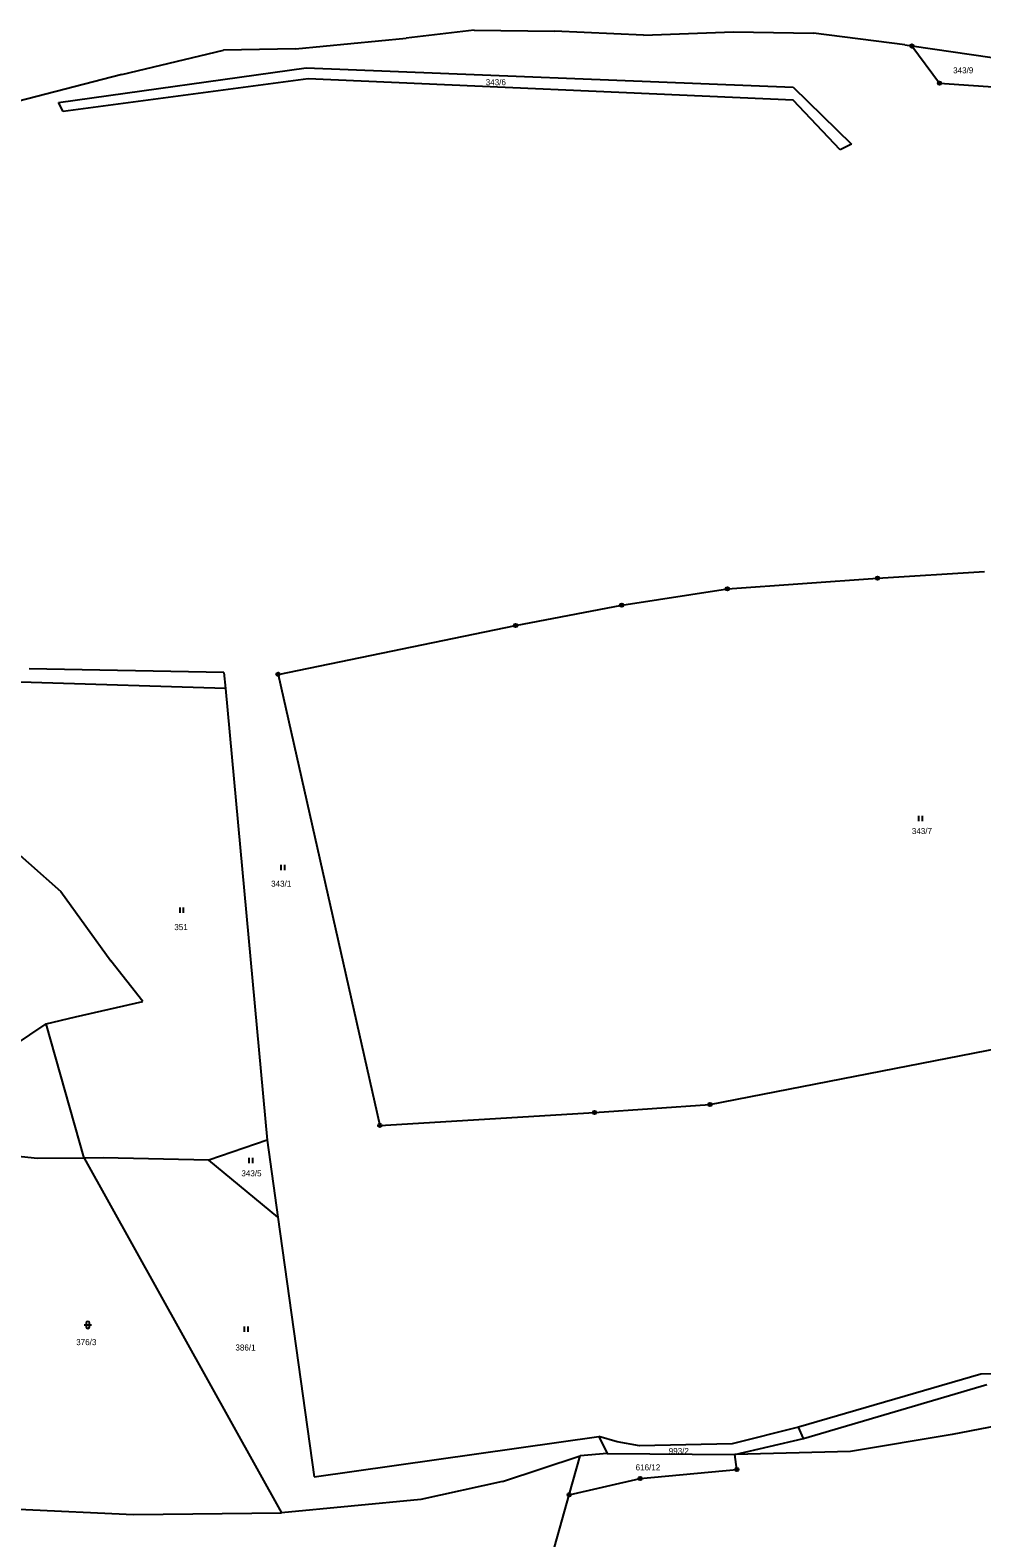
# Model space of a CAD drawing. Extents: x -754970 to -752637, y -970569 to -968179.
# Drawn here: x -754459.1 to -754191, y -968939.8 to -968515.2 of the extents above; entities that cross this region are included whole.
import ezdxf
from ezdxf.enums import TextEntityAlignment as Align

# ---------------------------------------------------------------- set-up
doc = ezdxf.new("R2010")
doc.units = 0
doc.header["$LTSCALE"] = 0.68
for name, color, linetype, lineweight in [('1', 7, 'Continuous', 25), ('3', 7, 'Continuous', 25), ('8', 7, 'Continuous', 25)]:
    doc.layers.add(name, color=color, linetype=linetype, lineweight=lineweight)
doc.layers.add('2', color=7, linetype='Continuous')

msp = doc.modelspace()

# ---------------------------------------------------------------- linework, layer by layer
at = {"layer": '1'}
for p, q in [((-754334.06, -968515.2), (-754353.18, -968517.43)), ((-754334.06, -968515.2), (-754311.42, -968515.52)), ((-754286.27, -968516.63), (-754311.42, -968515.52)), ((-754286.27, -968516.63), (-754260.98, -968515.67)), ((-754260.98, -968515.67), (-754238.42, -968516.06)), ((-754212.69, -968519.37), (-754238.42, -968516.06)), ((-754384.36, -968520.42), (-754353.18, -968517.43)), ((-754212.69, -968519.37), (-754210.71, -968519.66)), ((-754210.71, -968519.66), (-754188.09, -968522.93)), ((-754210.71, -968519.66), (-754202.9, -968530.13)), ((-754433.35, -968527.73), (-754404.65, -968520.82)), ((-754384.36, -968520.42), (-754404.65, -968520.82)), ((-754433.35, -968527.73), (-754462.74, -968535.32)), ((-754451.15, -968535.59), (-754381.35, -968525.78)), ((-754381.35, -968525.78), (-754244.11, -968531.24)), ((-754380.77, -968528.88), (-754449.8, -968538.11)), ((-754244.18, -968534.92), (-754380.77, -968528.88)), ((-754244.11, -968531.24), (-754227.7, -968547.33)), ((-754202.9, -968530.13), (-754183.76, -968531.43)), ((-754449.8, -968538.11), (-754451.15, -968535.59)), ((-754230.91, -968548.91), (-754244.18, -968534.92)), ((-754227.7, -968547.33), (-754230.91, -968548.91)), ((-754220.37, -968669.52), (-754190.19, -968667.68)), ((-754292.45, -968677.13), (-754262.67, -968672.55)), ((-754262.67, -968672.55), (-754220.37, -968669.52)), ((-754322.36, -968682.86), (-754292.45, -968677.13)), ((-754389.3, -968696.62), (-754322.36, -968682.86)), ((-754458.84, -968698.91), (-754526.43, -968697.59)), ((-754404.56, -968696.08), (-754459.46, -968695.1)), ((-754404.56, -968696.08), (-754404.12, -968700.59)), ((-754389.3, -968696.62), (-754360.62, -968823.65)), ((-754404.12, -968700.59), (-754458.84, -968698.91)), ((-754404.12, -968700.59), (-754392.37, -968827.82)), ((-754499.27, -968714.58), (-754450.52, -968757.76)), ((-754450.52, -968757.76), (-754436.37, -968777.32)), ((-754427.43, -968788.74), (-754436.37, -968777.32)), ((-754446.37, -968793.08), (-754427.43, -968788.74)), ((-754470.43, -968805.64), (-754454.59, -968795.02)), ((-754454.59, -968795.02), (-754446.37, -968793.08)), ((-754443.88, -968832.87), (-754454.59, -968795.02)), ((-754267.58, -968817.77), (-754185.68, -968801.8)), ((-754360.62, -968823.65), (-754300.13, -968820)), ((-754300.13, -968820), (-754267.58, -968817.77)), ((-754457.06, -968832.97), (-754499.36, -968828.55)), ((-754392.37, -968827.82), (-754408.84, -968833.4)), ((-754392.37, -968827.82), (-754389.33, -968849.47)), ((-754443.88, -968832.87), (-754457.06, -968832.97)), ((-754438.57, -968832.78), (-754443.88, -968832.87)), ((-754443.88, -968832.87), (-754388.34, -968932.75)), ((-754408.84, -968833.4), (-754438.57, -968832.78)), ((-754389.33, -968849.47), (-754408.84, -968833.4)), ((-754389.33, -968849.47), (-754379.07, -968922.66)), ((-754191.24, -968893.69), (-754242.67, -968908.61)), ((-754136.79, -968893.18), (-754191.24, -968893.69)), ((-754241.27, -968911.79), (-754189.58, -968896.62)), ((-754150.53, -968901.2), (-754199.37, -968910.74)), ((-754242.67, -968908.61), (-754261.37, -968913.34)), ((-754241.27, -968911.79), (-754242.67, -968908.61)), ((-754199.37, -968910.74), (-754227.98, -968915.46)), ((-754379.07, -968922.66), (-754298.86, -968911.22)), ((-754298.86, -968911.22), (-754296.56, -968916.06)), ((-754293.73, -968912.8), (-754298.86, -968911.22)), ((-754287.44, -968913.88), (-754293.73, -968912.8)), ((-754261.37, -968913.34), (-754287.44, -968913.88)), ((-754260.6, -968916.29), (-754241.27, -968911.79)), ((-754326.03, -968923.97), (-754304.17, -968916.69)), ((-754307.25, -968927.67), (-754304.17, -968916.69)), ((-754296.56, -968916.06), (-754304.17, -968916.69)), ((-754296.56, -968916.06), (-754260.6, -968916.29)), ((-754227.98, -968915.46), (-754260.6, -968916.29)), ((-754260.01, -968920.54), (-754260.6, -968916.29)), ((-754307.25, -968927.67), (-754287.26, -968923.08)), ((-754287.26, -968923.08), (-754260.01, -968920.54)), ((-754326.03, -968923.97), (-754349.04, -968929.02)), ((-754315.88, -968958.49), (-754307.25, -968927.67)), ((-754462.39, -968931.72), (-754430.03, -968933.19)), ((-754349.04, -968929.02), (-754388.34, -968932.75)), ((-754430.03, -968933.19), (-754388.34, -968932.75))]:
    msp.add_line(p, q, dxfattribs=at)
at = {"layer": '3'}
for p, q in [((-754208.701, -968737.95), (-754208.701, -968736.45)), ((-754207.7, -968737.95), (-754207.7, -968736.45)), ((-754388.381, -968751.78), (-754388.381, -968750.28)), ((-754387.38, -968751.78), (-754387.38, -968750.28)), ((-754416.891, -968763.75), (-754416.891, -968762.25)), ((-754415.89, -968763.75), (-754415.89, -968762.25)), ((-754397.431, -968834.25), (-754397.431, -968832.75)), ((-754396.43, -968834.25), (-754396.43, -968832.75)), ((-754443.881, -968879.851), (-754441.879, -968879.851)), ((-754443.381, -968879.351), (-754443.381, -968880.352)), ((-754442.379, -968880.352), (-754442.379, -968879.351)), ((-754398.721, -968881.76), (-754398.721, -968880.26)), ((-754397.72, -968881.76), (-754397.72, -968880.26))]:
    msp.add_line(p, q, dxfattribs=at)
for centre, start, end in [((-754442.88, -968879.3509), 0, 180), ((-754442.88, -968880.3509), 180, 359.98789)]:
    msp.add_arc(centre, 0.5, start, end, dxfattribs=at)
at = {"layer": '8'}
for centre, radius in [((-754210.71, -968519.6599), 0.5), ((-754210.71, -968519.6599), 0.0303), ((-754202.9, -968530.1299), 0.5), ((-754202.9, -968530.1299), 0.0303), ((-754262.67, -968672.5499), 0.5), ((-754262.67, -968672.5499), 0.0303), ((-754220.37, -968669.5199), 0.5), ((-754220.37, -968669.5199), 0.0303), ((-754292.45, -968677.1299), 0.5), ((-754292.45, -968677.1299), 0.0303), ((-754322.36, -968682.8599), 0.5), ((-754322.36, -968682.8599), 0.0303), ((-754389.3, -968696.6199), 0.5), ((-754389.3, -968696.6199), 0.0303), ((-754267.58, -968817.7699), 0.5), ((-754300.13, -968819.9999), 0.5), ((-754300.13, -968819.9999), 0.0303), ((-754267.58, -968817.7699), 0.0303), ((-754360.62, -968823.6499), 0.5), ((-754360.62, -968823.6499), 0.0303), ((-754287.26, -968923.0799), 0.5), ((-754287.26, -968923.0799), 0.0303), ((-754260.01, -968920.5399), 0.5), ((-754260.01, -968920.5399), 0.0303), ((-754307.25, -968927.6699), 0.5), ((-754307.25, -968927.6699), 0.0303)]:
    msp.add_circle(centre, radius, dxfattribs=at)

# ---------------------------------------------------------------- texts
at = {"layer": '2'}
for s, p in [('343/9', (-754196.22, -968527.355)), ('343/6', (-754327.92, -968530.705)), ('343/7', (-754207.85, -968741.605)), ('343/1', (-754388.4, -968756.425)), ('351', (-754416.619, -968768.655)), ('343/5', (-754396.78, -968837.995)), ('376/3', (-754443.33, -968885.535)), ('386/1', (-754398.46, -968887.055)), ('993/2', (-754276.37, -968916.195)), ('616/12', (-754285.06, -968920.805))]:
    msp.add_text(s, height=1.7, dxfattribs=at).set_placement(p, align=Align.CENTER)

doc.saveas('drawing.dxf')
